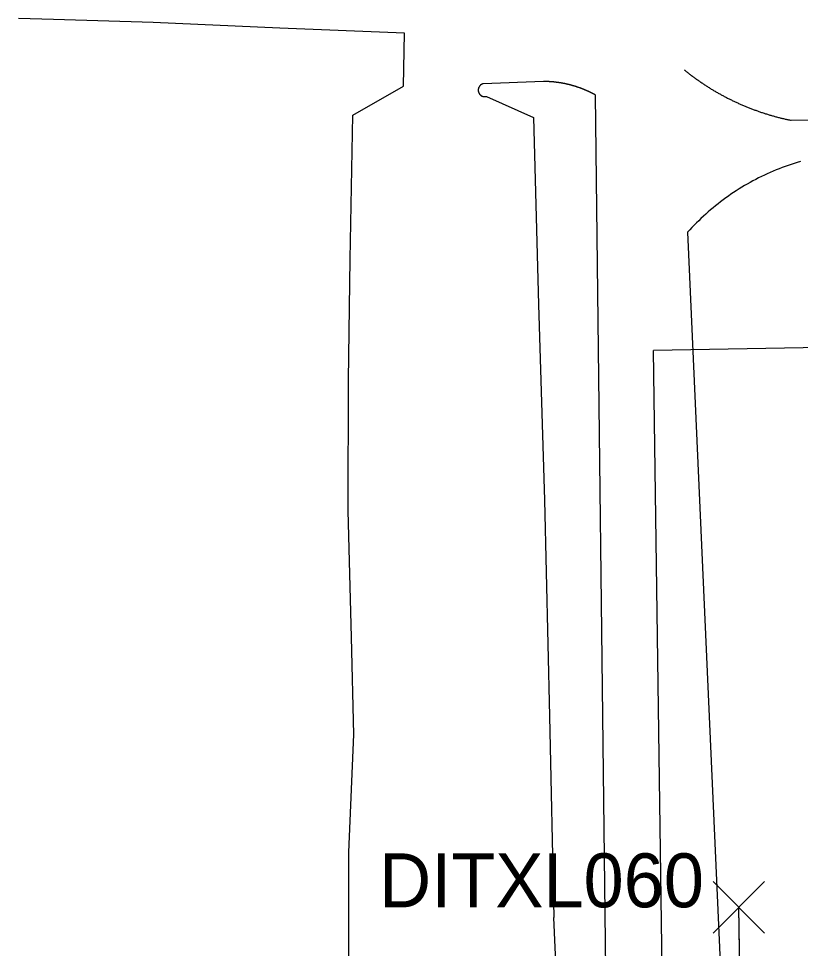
# Model space of a CAD drawing. Extents: x 2287043 to 2296348, y 637947 to 641293.
# Drawn here: x 2287190.3 to 2287393.1, y 640344.4 to 640585.7 of the extents above; entities that cross this region are included whole.
import ezdxf

# ---------------------------------------------------------------- set-up
doc = ezdxf.new("R2010")
doc.units = 0
for name, color, linetype in [('DR_P_Drainage_Area', 7, 'Continuous'), ('GK_Visualization', 7, 'Continuous'), ('SC_Scratch4', 7, 'Continuous'), ('SC_Scratch7', 7, 'Continuous')]:
    doc.layers.add(name, color=color, linetype=linetype)

msp = doc.modelspace()

# ---------------------------------------------------------------- linework, layer by layer
at = {"layer": 'DR_P_Drainage_Area'}
for p in [(2287450.99, 640501.32), (2287357.3, 640335.57)]:
    msp.add_line(p, (2287354.99, 640499.61), dxfattribs=at)
at = {"layer": 'GK_Visualization'}
for p, q in [((2287370.48, 640348.39), (2287383.81, 640361.74)), ((2287370.48, 640361.74), (2287383.81, 640348.39)), ((2287378.35, 640275.48), (2287377.14, 640355.07))]:
    msp.add_line(p, q, dxfattribs=at)
at = {"layer": 'SC_Scratch4'}
for p, q in [((2287342.63, 640335.31), (2287339.95, 640565.88)), ((2287363.81, 640530.27), (2287372.48, 640335.71)), ((2287331.43, 640305.7), (2287329.09, 640352.44))]:
    msp.add_line(p, q, dxfattribs=at)
for points in [[(2287284.57, 640247.19), (2287268.9, 640246.45), (2287270.15, 640278.98), (2287270.2, 640300.37), (2287276.32, 640300.86), (2287275.93, 640339.7), (2287275.97, 640369.4), (2287277.25, 640399.95), (2287276.62, 640425.18), (2287275.79, 640457.99), (2287275.88, 640491.85), (2287276.31, 640523.32), (2287276.98, 640560.61), (2287290.08, 640568.15), (2287290.42, 640581.97), (2287258, 640583.22), (2287225.17, 640584.67), (2287199.3, 640585.49), (2287190.26, 640585.71)], [(2287362.9, 640572.45), (2287363.08, 640572.31), (2287363.26, 640572.17), (2287363.44, 640572.02), (2287363.61, 640571.88), (2287363.79, 640571.74), (2287363.97, 640571.6), (2287364.15, 640571.46), (2287364.33, 640571.32), (2287364.52, 640571.18), (2287364.7, 640571.04), (2287364.88, 640570.91), (2287365.06, 640570.77), (2287365.25, 640570.63), (2287365.43, 640570.5), (2287365.61, 640570.36), (2287365.8, 640570.23), (2287365.98, 640570.09), (2287366.17, 640569.96), (2287366.36, 640569.83), (2287366.54, 640569.7), (2287366.73, 640569.57), (2287366.92, 640569.44), (2287367.11, 640569.31), (2287367.29, 640569.18), (2287367.48, 640569.05), (2287367.67, 640568.92), (2287367.86, 640568.79), (2287368.05, 640568.67), (2287368.24, 640568.54), (2287368.43, 640568.42), (2287368.63, 640568.29), (2287368.82, 640568.17), (2287369.01, 640568.05), (2287369.2, 640567.93), (2287369.4, 640567.8), (2287369.59, 640567.68), (2287369.79, 640567.56), (2287369.98, 640567.44), (2287370.18, 640567.33), (2287370.37, 640567.21), (2287370.57, 640567.09), (2287370.76, 640566.97), (2287370.96, 640566.86), (2287371.16, 640566.74), (2287371.36, 640566.63), (2287371.55, 640566.51), (2287371.75, 640566.4), (2287371.95, 640566.29), (2287372.15, 640566.18), (2287372.35, 640566.07), (2287372.55, 640565.96), (2287372.75, 640565.85), (2287372.95, 640565.74), (2287373.15, 640565.63), (2287373.35, 640565.52), (2287373.56, 640565.42), (2287373.76, 640565.31), (2287373.96, 640565.2), (2287374.16, 640565.1), (2287374.37, 640565), (2287374.57, 640564.89), (2287374.77, 640564.79), (2287374.98, 640564.69), (2287375.18, 640564.59), (2287375.39, 640564.49), (2287375.6, 640564.39), (2287375.8, 640564.29), (2287376.01, 640564.19), (2287376.21, 640564.09), (2287376.42, 640564), (2287376.63, 640563.9), (2287376.84, 640563.81), (2287377.04, 640563.71), (2287377.25, 640563.62), (2287377.46, 640563.53), (2287377.67, 640563.43), (2287377.88, 640563.34), (2287378.09, 640563.25), (2287378.3, 640563.16), (2287378.51, 640563.07), (2287378.72, 640562.99), (2287378.93, 640562.9), (2287379.14, 640562.81), (2287379.35, 640562.73), (2287379.57, 640562.64), (2287379.78, 640562.56), (2287379.99, 640562.47), (2287380.2, 640562.39), (2287380.42, 640562.31), (2287380.63, 640562.23), (2287380.84, 640562.14), (2287381.06, 640562.06), (2287381.27, 640561.99), (2287381.49, 640561.91), (2287381.7, 640561.83), (2287381.92, 640561.75), (2287382.13, 640561.68), (2287382.35, 640561.6), (2287382.56, 640561.53), (2287382.78, 640561.45), (2287382.99, 640561.38), (2287383.21, 640561.31), (2287383.43, 640561.24), (2287383.65, 640561.16), (2287383.86, 640561.09), (2287384.08, 640561.03), (2287384.3, 640560.96), (2287384.52, 640560.89), (2287384.73, 640560.82), (2287384.95, 640560.76), (2287385.17, 640560.69), (2287385.39, 640560.63), (2287385.61, 640560.56), (2287385.83, 640560.5), (2287386.05, 640560.44), (2287386.27, 640560.38), (2287386.49, 640560.32), (2287386.71, 640560.26), (2287386.93, 640560.2), (2287387.15, 640560.14), (2287387.37, 640560.08), (2287387.59, 640560.02), (2287387.82, 640559.97), (2287388.04, 640559.91), (2287388.26, 640559.86), (2287388.48, 640559.8), (2287388.7, 640559.75), (2287388.93, 640559.7), (2287389.15, 640559.65), (2287389.37, 640559.6), (2287389.59, 640559.55), (2287389.82, 640559.5), (2287390.04, 640559.45), (2287390.26, 640559.4), (2287390.49, 640559.36), (2287390.71, 640559.31)], [(2287326.48, 640569.39), (2287310.83, 640568.8)], [(2287339.95, 640565.88), (2287339.87, 640565.93), (2287339.78, 640565.98), (2287339.7, 640566.02), (2287339.61, 640566.07), (2287339.53, 640566.11), (2287339.44, 640566.16), (2287339.36, 640566.2), (2287339.27, 640566.25), (2287339.19, 640566.29), (2287339.1, 640566.33), (2287339.02, 640566.38), (2287338.93, 640566.42), (2287338.84, 640566.46), (2287338.76, 640566.51), (2287338.67, 640566.55), (2287338.58, 640566.59), (2287338.5, 640566.63), (2287338.41, 640566.67), (2287338.32, 640566.71), (2287338.24, 640566.76), (2287338.15, 640566.8), (2287338.06, 640566.84), (2287337.97, 640566.88), (2287337.89, 640566.92), (2287337.8, 640566.96), (2287337.71, 640566.99), (2287337.62, 640567.03), (2287337.53, 640567.07), (2287337.45, 640567.11), (2287337.36, 640567.15), (2287337.27, 640567.18), (2287337.18, 640567.22), (2287337.09, 640567.26), (2287337, 640567.3), (2287336.91, 640567.33), (2287336.82, 640567.37), (2287336.73, 640567.4), (2287336.64, 640567.44), (2287336.56, 640567.47), (2287336.47, 640567.51), (2287336.38, 640567.54), (2287336.29, 640567.58), (2287336.2, 640567.61), (2287336.11, 640567.64), (2287336.01, 640567.68), (2287335.92, 640567.71), (2287335.83, 640567.74), (2287335.74, 640567.78), (2287335.65, 640567.81), (2287335.56, 640567.84), (2287335.47, 640567.87), (2287335.38, 640567.9), (2287335.29, 640567.93), (2287335.2, 640567.96), (2287335.1, 640567.99), (2287335.01, 640568.02), (2287334.92, 640568.05), (2287334.83, 640568.08), (2287334.74, 640568.11), (2287334.65, 640568.14), (2287334.55, 640568.17), (2287334.46, 640568.2), (2287334.37, 640568.22), (2287334.28, 640568.25), (2287334.18, 640568.28), (2287334.09, 640568.3), (2287334, 640568.33), (2287333.91, 640568.36), (2287333.81, 640568.38), (2287333.72, 640568.41), (2287333.63, 640568.43), (2287333.53, 640568.46), (2287333.44, 640568.48), (2287333.35, 640568.51), (2287333.25, 640568.53), (2287333.16, 640568.55), (2287333.07, 640568.58), (2287332.97, 640568.6), (2287332.88, 640568.62), (2287332.79, 640568.64), (2287332.69, 640568.67), (2287332.6, 640568.69), (2287332.5, 640568.71), (2287332.41, 640568.73), (2287332.32, 640568.75), (2287332.22, 640568.77), (2287332.13, 640568.79), (2287332.03, 640568.81), (2287331.94, 640568.83), (2287331.84, 640568.85), (2287331.75, 640568.87), (2287331.65, 640568.89), (2287331.56, 640568.9), (2287331.47, 640568.92), (2287331.37, 640568.94), (2287331.28, 640568.96), (2287331.18, 640568.97), (2287331.09, 640568.99), (2287330.99, 640569.01), (2287330.9, 640569.02), (2287330.8, 640569.04), (2287330.71, 640569.05), (2287330.61, 640569.07), (2287330.51, 640569.08), (2287330.42, 640569.1), (2287330.32, 640569.11), (2287330.23, 640569.12), (2287330.13, 640569.14), (2287330.04, 640569.15), (2287329.94, 640569.16), (2287329.85, 640569.17), (2287329.75, 640569.19), (2287329.65, 640569.2), (2287329.56, 640569.21), (2287329.46, 640569.22), (2287329.37, 640569.23), (2287329.27, 640569.24), (2287329.18, 640569.25), (2287329.08, 640569.26), (2287328.98, 640569.27), (2287328.89, 640569.28), (2287328.79, 640569.29), (2287328.7, 640569.29), (2287328.6, 640569.3), (2287328.5, 640569.31), (2287328.41, 640569.32), (2287328.31, 640569.32), (2287328.22, 640569.33), (2287328.12, 640569.34), (2287328.02, 640569.34), (2287327.93, 640569.35), (2287327.83, 640569.35), (2287327.73, 640569.36), (2287327.64, 640569.36), (2287327.54, 640569.37), (2287327.45, 640569.37), (2287327.35, 640569.37), (2287327.25, 640569.38), (2287327.16, 640569.38), (2287327.06, 640569.38), (2287326.96, 640569.39), (2287326.87, 640569.39), (2287326.77, 640569.39), (2287326.67, 640569.39), (2287326.58, 640569.39), (2287326.48, 640569.39)], [(2287310.83, 640568.8), (2287310.8, 640568.8), (2287310.77, 640568.79), (2287310.75, 640568.78), (2287310.72, 640568.77), (2287310.69, 640568.77), (2287310.66, 640568.76), (2287310.63, 640568.75), (2287310.61, 640568.74), (2287310.58, 640568.73), (2287310.55, 640568.72), (2287310.52, 640568.7), (2287310.5, 640568.69), (2287310.47, 640568.68), (2287310.44, 640568.67), (2287310.42, 640568.65), (2287310.39, 640568.64), (2287310.36, 640568.63), (2287310.34, 640568.61), (2287310.31, 640568.6), (2287310.29, 640568.58), (2287310.26, 640568.56), (2287310.24, 640568.55), (2287310.21, 640568.53), (2287310.19, 640568.51), (2287310.17, 640568.5), (2287310.14, 640568.48), (2287310.12, 640568.46), (2287310.1, 640568.44), (2287310.08, 640568.42), (2287310.05, 640568.4), (2287310.03, 640568.38), (2287310.01, 640568.36), (2287309.99, 640568.34), (2287309.97, 640568.32), (2287309.95, 640568.3), (2287309.93, 640568.28), (2287309.91, 640568.25), (2287309.89, 640568.23), (2287309.87, 640568.21), (2287309.85, 640568.19), (2287309.84, 640568.16), (2287309.82, 640568.14), (2287309.8, 640568.11), (2287309.79, 640568.09), (2287309.77, 640568.06), (2287309.75, 640568.04), (2287309.74, 640568.01), (2287309.72, 640567.99), (2287309.71, 640567.96), (2287309.69, 640567.94), (2287309.68, 640567.91), (2287309.67, 640567.88), (2287309.66, 640567.86), (2287309.64, 640567.83), (2287309.63, 640567.8), (2287309.62, 640567.78), (2287309.61, 640567.75), (2287309.6, 640567.72), (2287309.59, 640567.69), (2287309.58, 640567.67), (2287309.57, 640567.64), (2287309.56, 640567.61), (2287309.56, 640567.58), (2287309.55, 640567.55), (2287309.54, 640567.52), (2287309.54, 640567.49), (2287309.53, 640567.47), (2287309.52, 640567.44), (2287309.52, 640567.41), (2287309.52, 640567.38), (2287309.51, 640567.35), (2287309.51, 640567.32), (2287309.51, 640567.29), (2287309.5, 640567.26), (2287309.5, 640567.23), (2287309.5, 640567.2), (2287309.5, 640567.17), (2287309.5, 640567.14), (2287309.5, 640567.11), (2287309.5, 640567.08), (2287309.5, 640567.05), (2287309.5, 640567.02), (2287309.51, 640567), (2287309.51, 640566.97), (2287309.51, 640566.94), (2287309.52, 640566.91), (2287309.52, 640566.88), (2287309.53, 640566.85), (2287309.53, 640566.82), (2287309.54, 640566.79), (2287309.55, 640566.76), (2287309.55, 640566.73), (2287309.56, 640566.71), (2287309.57, 640566.68), (2287309.58, 640566.65), (2287309.58, 640566.62), (2287309.59, 640566.59), (2287309.6, 640566.57), (2287309.61, 640566.54), (2287309.63, 640566.51), (2287309.64, 640566.48), (2287309.65, 640566.46), (2287309.66, 640566.43), (2287309.67, 640566.4), (2287309.69, 640566.38), (2287309.7, 640566.35), (2287309.72, 640566.32), (2287309.73, 640566.3), (2287309.74, 640566.27), (2287309.76, 640566.25), (2287309.78, 640566.22), (2287309.79, 640566.2), (2287309.81, 640566.17), (2287309.83, 640566.15), (2287309.84, 640566.13), (2287309.86, 640566.1), (2287309.88, 640566.08), (2287309.9, 640566.06), (2287309.92, 640566.04), (2287309.94, 640566.01), (2287309.96, 640565.99), (2287309.98, 640565.97), (2287310, 640565.95), (2287310.02, 640565.93), (2287310.04, 640565.91), (2287310.06, 640565.89), (2287310.09, 640565.87), (2287310.11, 640565.85), (2287310.13, 640565.83), (2287310.15, 640565.81), (2287310.18, 640565.79), (2287310.2, 640565.78), (2287310.23, 640565.76), (2287310.25, 640565.74), (2287310.27, 640565.73), (2287310.3, 640565.71), (2287310.32, 640565.7), (2287310.35, 640565.68), (2287310.38, 640565.67), (2287310.4, 640565.65), (2287310.43, 640565.64), (2287310.45, 640565.63), (2287310.48, 640565.61), (2287310.51, 640565.6), (2287310.54, 640565.59), (2287310.56, 640565.58), (2287310.59, 640565.57), (2287310.62, 640565.56), (2287310.65, 640565.55), (2287310.67, 640565.54), (2287310.7, 640565.53), (2287310.73, 640565.52), (2287310.76, 640565.51), (2287310.79, 640565.51), (2287310.82, 640565.5), (2287310.84, 640565.49), (2287310.87, 640565.49), (2287310.9, 640565.48), (2287310.93, 640565.48), (2287310.96, 640565.47), (2287310.99, 640565.47), (2287311.02, 640565.47), (2287311.05, 640565.46), (2287311.08, 640565.46), (2287311.11, 640565.46), (2287311.14, 640565.46), (2287311.17, 640565.46), (2287311.2, 640565.46), (2287311.23, 640565.46), (2287311.25, 640565.46), (2287311.28, 640565.46), (2287311.31, 640565.46), (2287311.34, 640565.46), (2287311.37, 640565.47), (2287311.4, 640565.47), (2287311.43, 640565.47), (2287311.46, 640565.48), (2287311.49, 640565.48), (2287311.52, 640565.49), (2287311.55, 640565.49), (2287311.58, 640565.5), (2287311.6, 640565.51), (2287311.63, 640565.51), (2287311.66, 640565.52)], [(2287311.66, 640565.52), (2287323.84, 640560.02), (2287325.11, 640511.48), (2287326.67, 640460.71), (2287328.04, 640404.67), (2287329.09, 640352.44)], [(2287390.71, 640559.31), (2287426.55, 640559.63), (2287479.85, 640560.04), (2287521.53, 640559.64), (2287571.52, 640559.74), (2287596.37, 640560.98)], [(2287393.09, 640548.63), (2287392.29, 640548.4), (2287391.5, 640548.15), (2287390.71, 640547.89), (2287389.92, 640547.62), (2287389.13, 640547.34), (2287388.35, 640547.05), (2287387.57, 640546.75), (2287386.8, 640546.44), (2287386.03, 640546.12), (2287385.27, 640545.79), (2287384.5, 640545.45), (2287383.75, 640545.09), (2287383, 640544.73), (2287382.25, 640544.36), (2287381.51, 640543.98), (2287380.77, 640543.59), (2287380.04, 640543.19), (2287379.32, 640542.78), (2287378.6, 640542.36), (2287377.88, 640541.93), (2287377.17, 640541.5), (2287376.47, 640541.05), (2287375.77, 640540.59), (2287375.08, 640540.13), (2287374.4, 640539.65), (2287373.72, 640539.17), (2287373.04, 640538.67), (2287372.38, 640538.17), (2287371.72, 640537.66), (2287371.07, 640537.14), (2287370.42, 640536.62), (2287369.78, 640536.08), (2287369.15, 640535.53), (2287368.53, 640534.98), (2287367.91, 640534.42), (2287367.3, 640533.85), (2287366.7, 640533.27), (2287366.11, 640532.69), (2287365.52, 640532.1), (2287364.94, 640531.5), (2287364.37, 640530.89), (2287363.81, 640530.27)]]:
    msp.add_lwpolyline(points, dxfattribs=at)
at = {"layer": 'SC_Scratch7'}
msp.add_lwpolyline([(2287381.53, 640227.99), (2287380.95, 640233.1), (2287379.18, 640240.28), (2287378.35, 640275.48), (2287377.14, 640355.07)], dxfattribs=at)

# ---------------------------------------------------------------- texts
at = {"layer": 'GK_Visualization'}
msp.add_text('DITXL060', height=14, dxfattribs=at).set_placement((2287283.78, 640355.07))

doc.saveas('drawing.dxf')
